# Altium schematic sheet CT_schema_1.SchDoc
size 515 x 464 mm
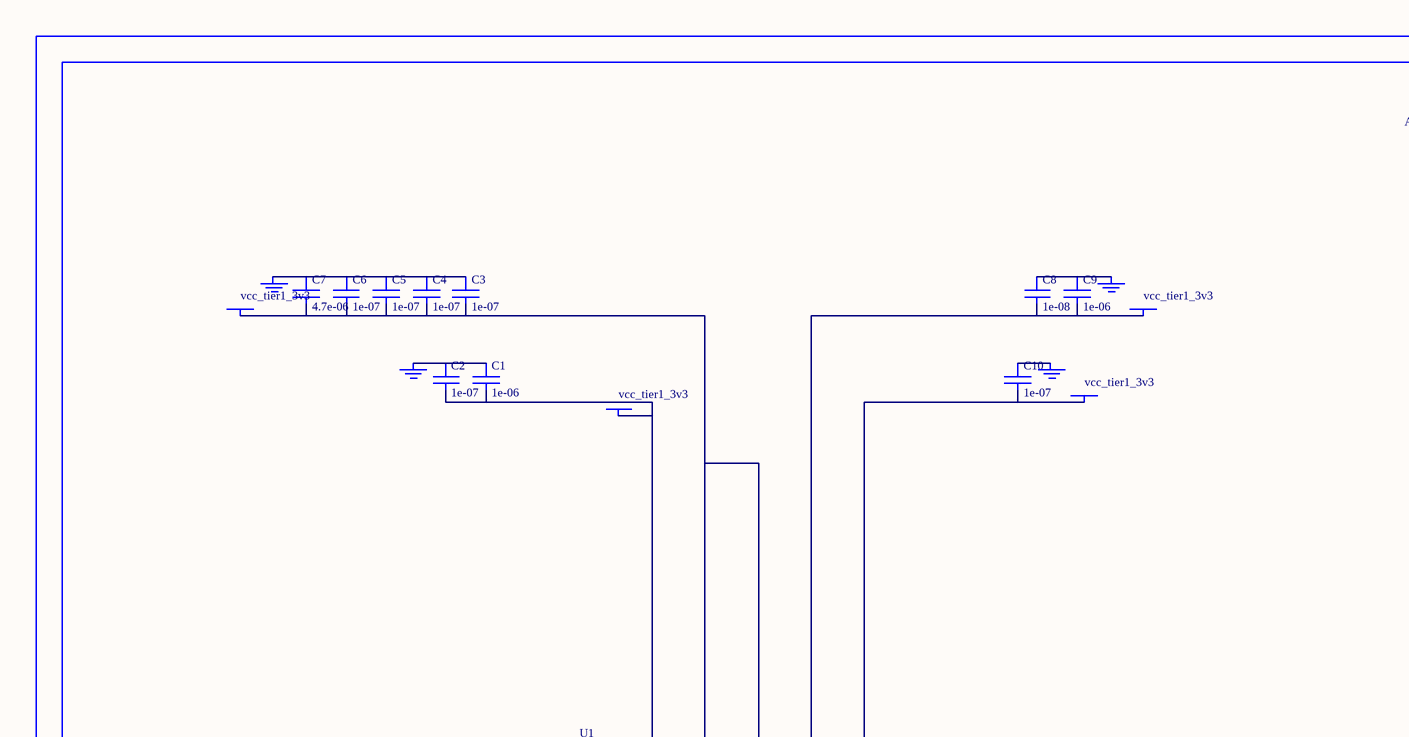
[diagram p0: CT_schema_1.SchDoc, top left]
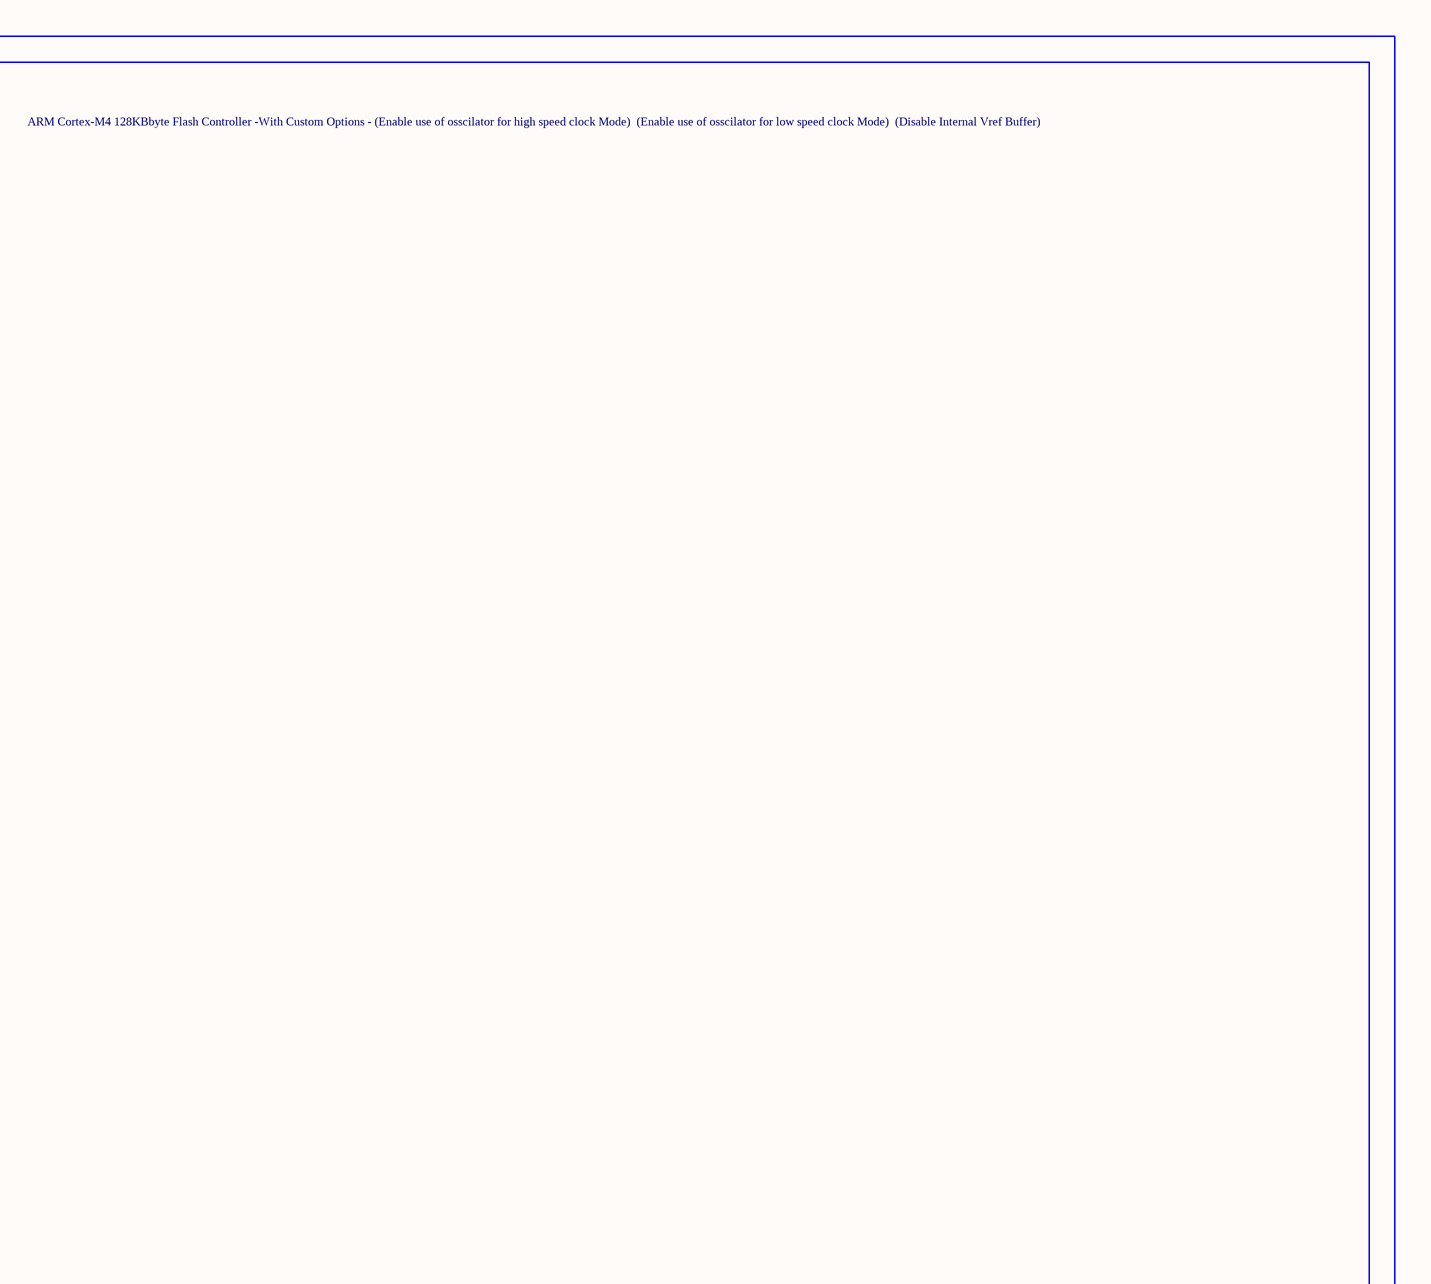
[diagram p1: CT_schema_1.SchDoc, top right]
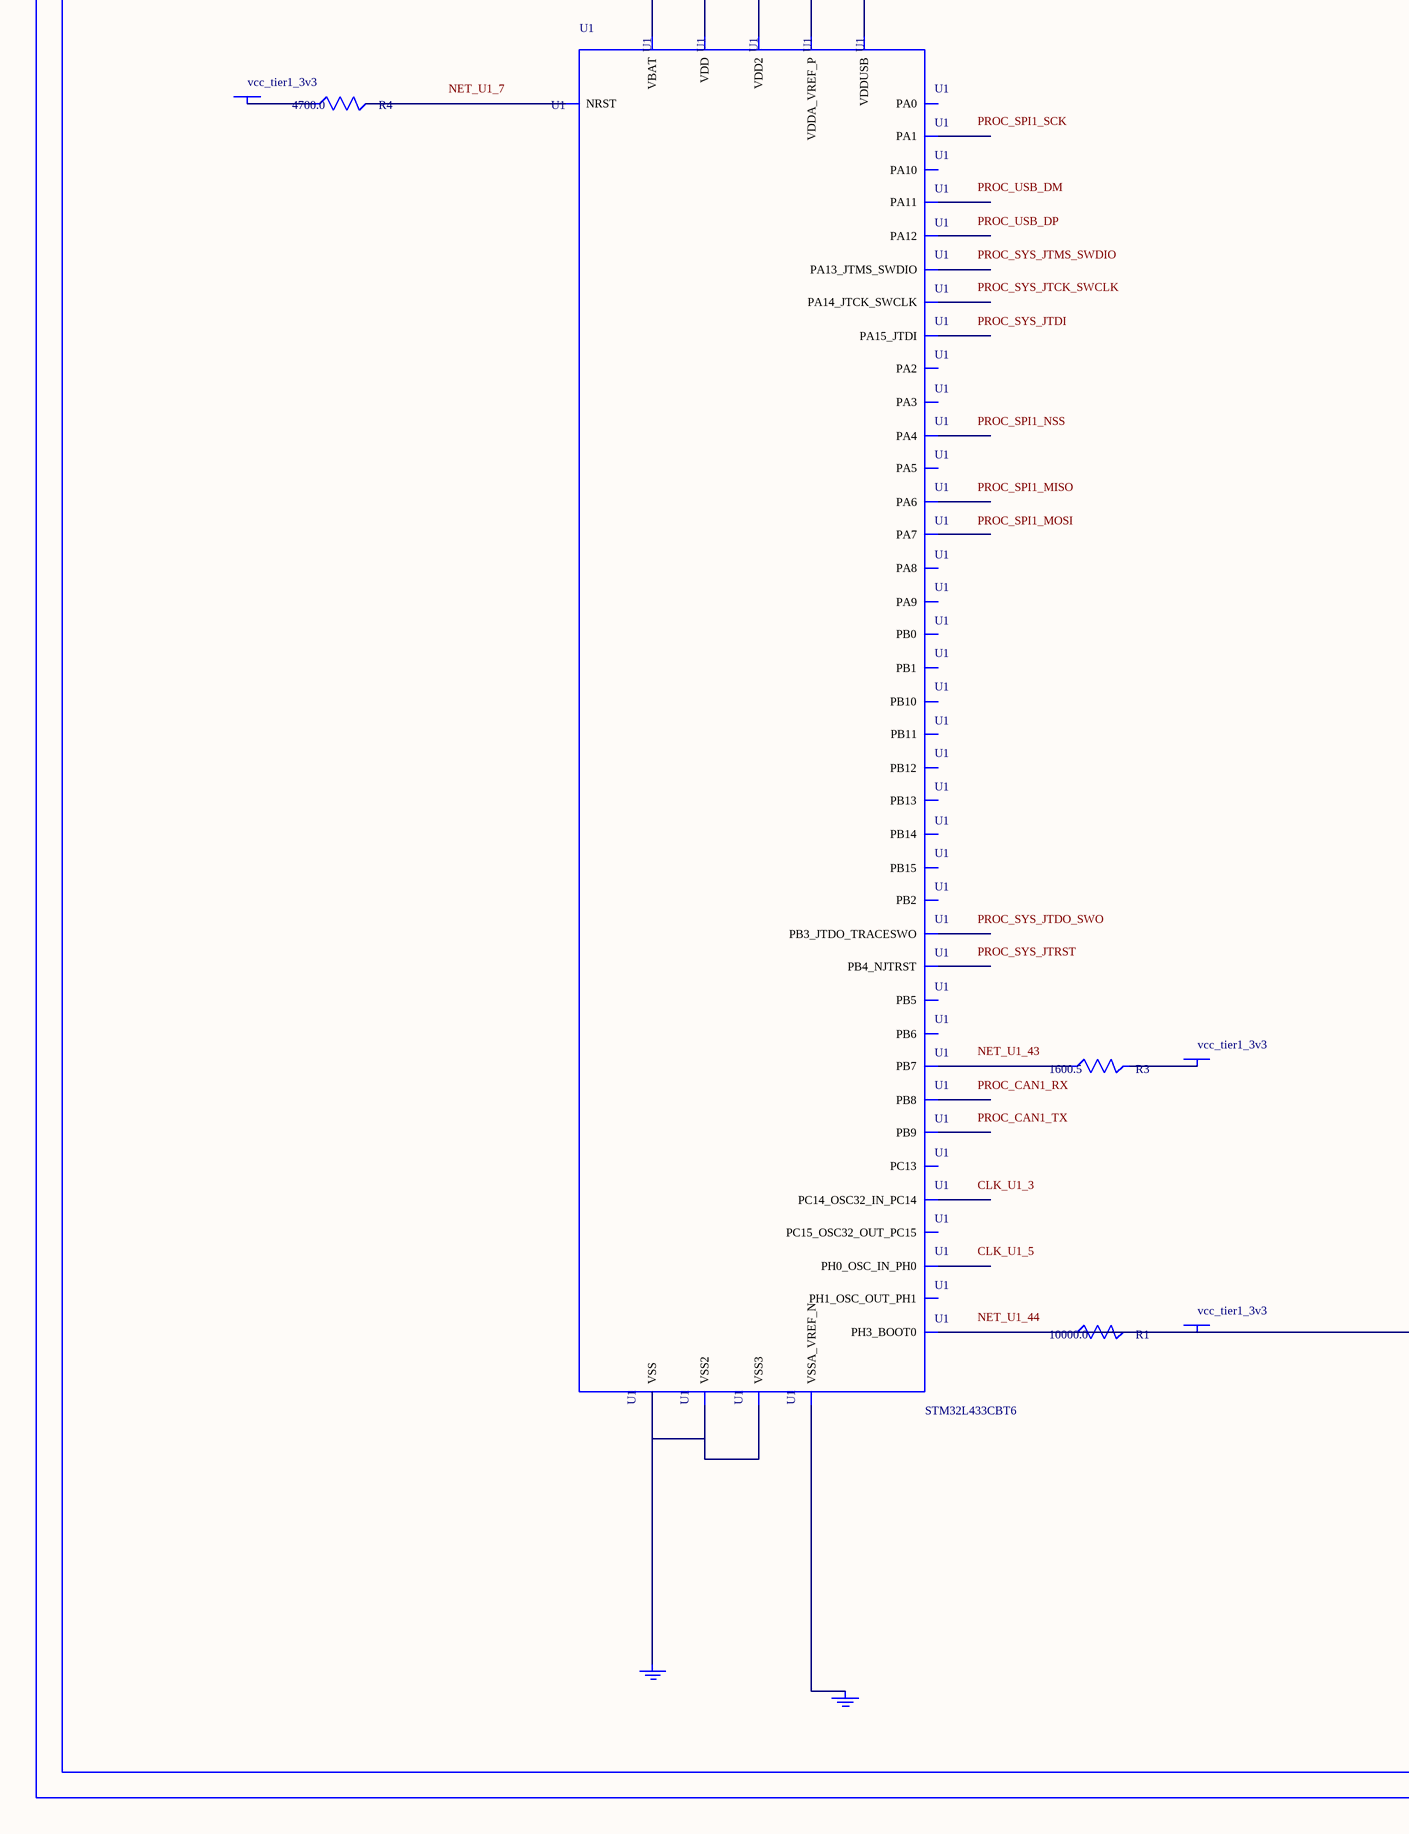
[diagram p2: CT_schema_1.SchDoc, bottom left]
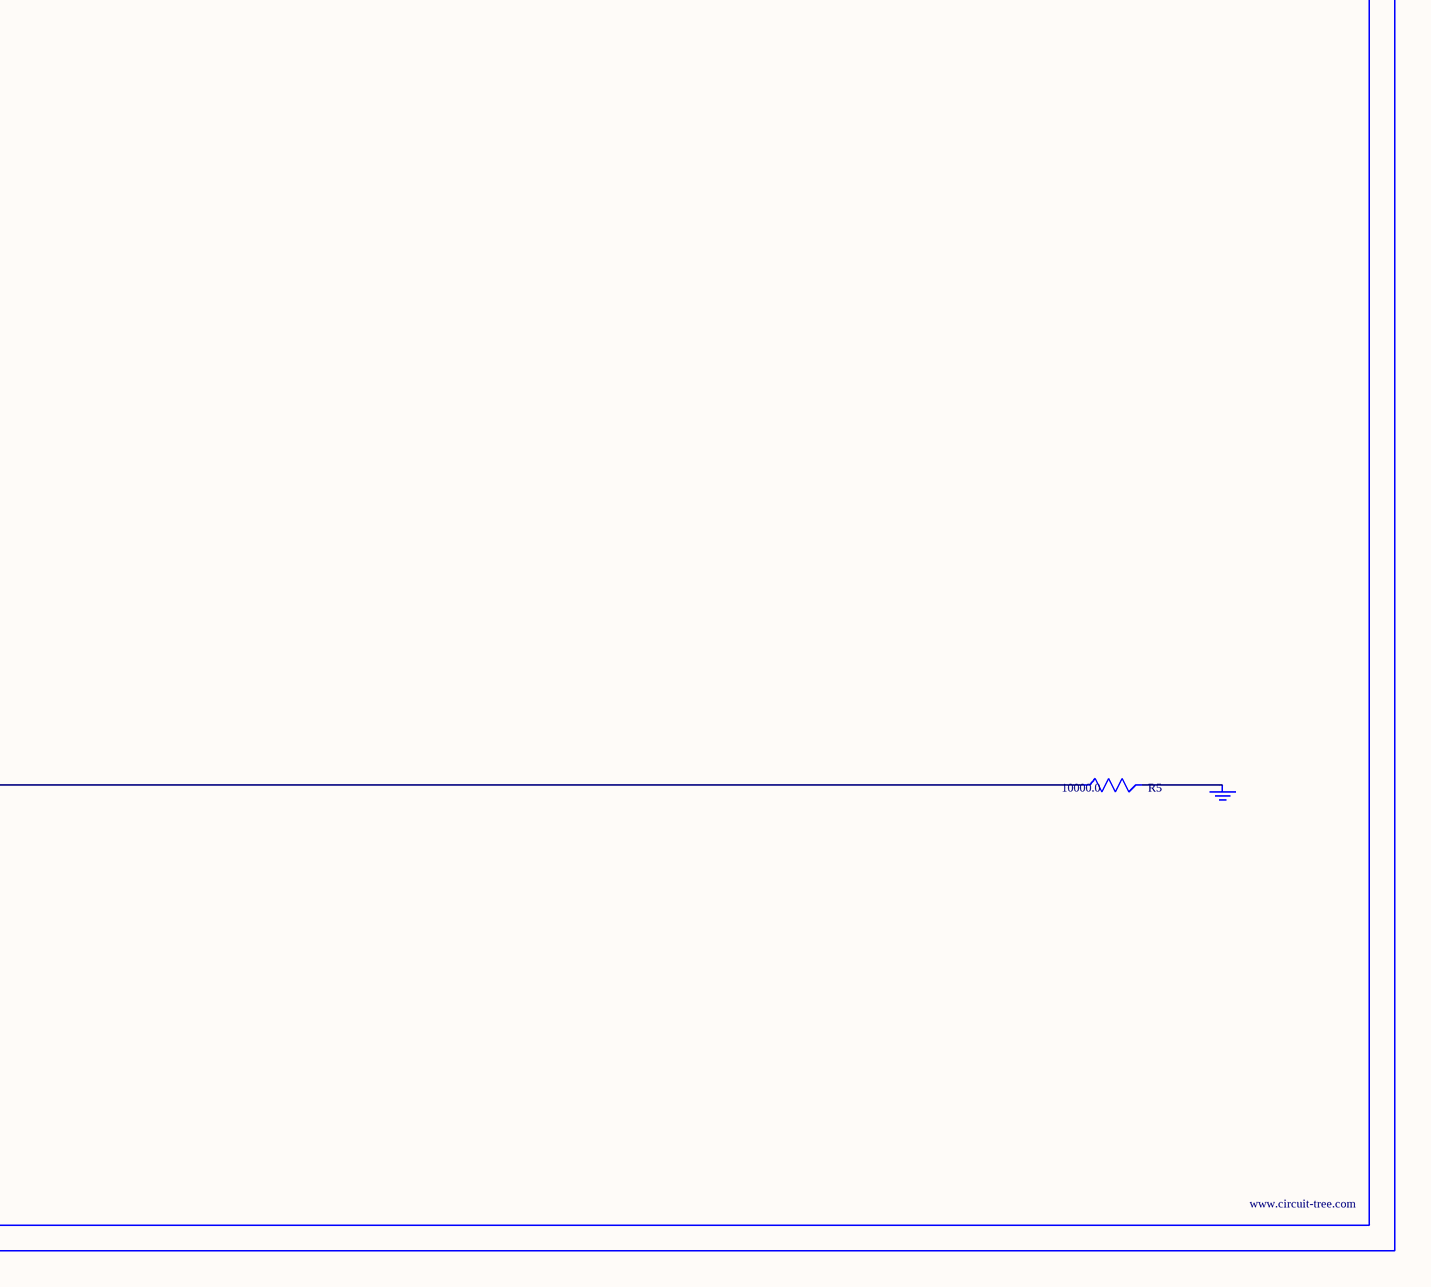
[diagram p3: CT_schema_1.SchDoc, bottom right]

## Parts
BORDER0  (no value)
C1  1e-06  [C0603]
C2  1e-07  [C0603]
C3  1e-07  [C0603]
C4  1e-07  [C0603]
C5  1e-07  [C0603]
C6  1e-07  [C0603]
C7  4.7e-06  [C0603]
C8  1e-08  [C0603]
C9  1e-06  [C0603]
C10  1e-07  [C0603]
GND_INSTANCE_0_0  (no value)
GND_INSTANCE_0_1  (no value)
GND_INSTANCE_0_2  (no value)
GND_INSTANCE_0_3  (no value)
GND_INSTANCE_0_4  (no value)
GND_INSTANCE_0_5  (no value)
GND_INSTANCE_0_6  (no value)
POWER_INSTANCE_0_0  vcc_tier1_3v3
POWER_INSTANCE_0_1  vcc_tier1_3v3
POWER_INSTANCE_0_2  vcc_tier1_3v3
POWER_INSTANCE_0_3  vcc_tier1_3v3
POWER_INSTANCE_0_4  vcc_tier1_3v3
POWER_INSTANCE_0_5  vcc_tier1_3v3
POWER_INSTANCE_0_6  vcc_tier1_3v3
R1  10000.0  [R0603]
R3  1600.5  [R0603]
R4  4700.0  [R0603]
R5  10000.0  [R0603]
U1  STM32L433CBT6  [LQFP48]

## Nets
NetC1_1: C1.1 C2.1 GND_INSTANCE_0_0.0(GND)
NetC1_2: C1.2 C2.2 POWER_INSTANCE_0_0.0(PWR) U1.1(VBAT)
NetC3_1: C3.1 C4.1 C5.1 C6.1 C7.1 GND_INSTANCE_0_3.0(GND)
NetC3_2: C3.2 C4.2 C5.2 C6.2 C7.2 POWER_INSTANCE_0_2.0(PWR) U1.24(VDD) U1.48(VDD2)
NetC8_1: C8.1 C9.1 GND_INSTANCE_0_2.0(GND)
NetC8_2: C8.2 C9.2 POWER_INSTANCE_0_1.0(PWR) U1.9(VDDA_VREF_P)
NetC10_1: C10.1 GND_INSTANCE_0_4.0(GND)
NetC10_2: C10.2 POWER_INSTANCE_0_3.0(PWR) U1.36(VDDUSB)
NetGND_INSTANCE_0_1_0: GND_INSTANCE_0_1.0(GND) U1.8(VSSA_VREF_N)
NetGND_INSTANCE_0_5_0: GND_INSTANCE_0_5.0(GND) R5.2
NetGND_INSTANCE_0_6_0: GND_INSTANCE_0_6.0(GND) U1.23(VSS) U1.35(VSS2) U1.47(VSS3)
NetPOWER_INSTANCE_0_4_0: POWER_INSTANCE_0_4.0(PWR) R4.1
NetPOWER_INSTANCE_0_5_0: POWER_INSTANCE_0_5.0(PWR) R3.2
NetPOWER_INSTANCE_0_6_0: POWER_INSTANCE_0_6.0(PWR) R1.1 R1.2 R5.1 U1.44(PH3_BOOT0)
NetR3_1: R3.1 U1.43(PB7)
NetR4_2: R4.2 U1.7(NRST)

Not connected (* = marked no-connect by the designer): U1 2(PC13) 3(PC14_OSC32_IN_PC14) 4(PC15_OSC32_OUT_PC15) 5(PH0_OSC_IN_PH0) 6(PH1_OSC_OUT_PH1) 10(PA0) 11(PA1) 12(PA2) 13(PA3) 14(PA4) 15(PA5) 16(PA6) 17(PA7) 18(PB0) 19(PB1) 20(PB2) 21(PB10) 22(PB11) 25(PB12) 26(PB13) 27(PB14) 28(PB15) 29(PA8) 30(PA9) 31(PA10) 32(PA11) 33(PA12) 34(PA13_JTMS_SWDIO) 37(PA14_JTCK_SWCLK) 38(PA15_JTDI) 39(PB3_JTDO_TRACESWO) 40(PB4_NJTRST) 41(PB5) 42(PB6) 45(PB8) 46(PB9)

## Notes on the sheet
- Labels drawn without touching a wire or pin: CLK_U1_3, CLK_U1_5, NET_U1_7, NET_U1_43, NET_U1_44, PROC_CAN1_RX, PROC_CAN1_TX, PROC_SPI1_MISO, PROC_SPI1_MOSI, PROC_SPI1_NSS, PROC_SPI1_SCK, PROC_SYS_JTCK_SWCLK, PROC_SYS_JTDI, PROC_SYS_JTDO_SWO, PROC_SYS_JTMS_SWDIO, PROC_SYS_JTRST, PROC_USB_DM, PROC_USB_DP

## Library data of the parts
BORDER0 = BORDER_PAGE0
C1 C9 = C0603C105K3RACTU
C2-C6 C10 = 06035C104K4Z2A
C7 = GRM188R6YA475KE15D
C8 = 06035C103K4Z2A
GND_INSTANCE_0_0-GND_INSTANCE_0_6 = GND
POWER_INSTANCE_0_0-POWER_INSTANCE_0_6 = PWR
R1 R5 = RC0603JR-0710KL
R3 = R3
R4 = RC0603JR-074K7L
